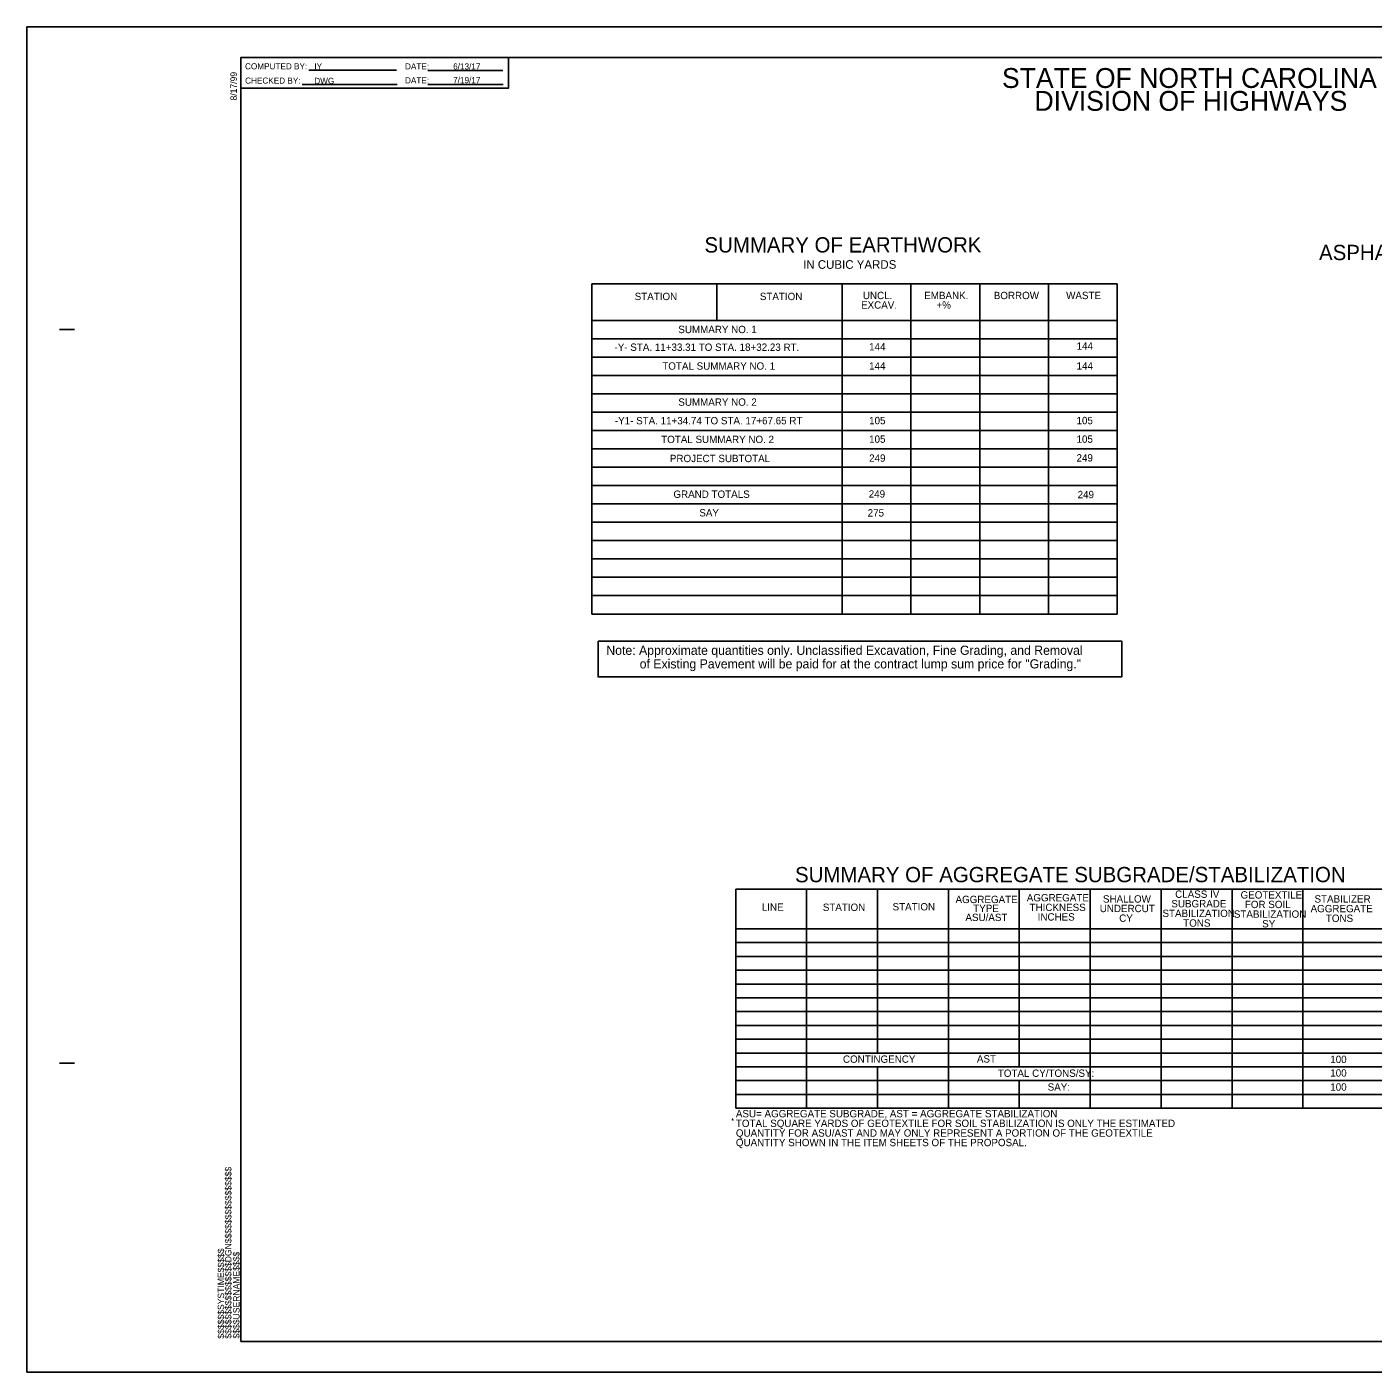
# Model space of a CAD drawing. Extents: x 573680 to 575380, y -53324 to -52224.
# Drawn here: x 573680 to 574781, y -53324 to -52224 of the extents above; entities that cross this region are included whole.
import ezdxf

# ---------------------------------------------------------------- set-up
doc = ezdxf.new("R2010")
doc.units = 0
for name, color, linetype in [('Prop Dimension Text', 7, 'Continuous'), ('Prop Grid Mask', 7, 'Continuous'), ('Prop XSC Text', 7, 'Continuous'), ('Sheet Block System Information CELL', 7, 'Continuous'), ('Sheet Data Field CELL', 7, 'Continuous'), ('Sheet Plan And Profile CELL', 7, 'Continuous'), ('Sheet Plot Border Outside CELL', 7, 'Continuous'), ('Sheet Summary Combination CELL', 7, 'Continuous'), ('Sheet Summary Combination Grid CELL', 7, 'Continuous')]:
    doc.layers.add(name, color=color, linetype=linetype)

msp = doc.modelspace()

# ---------------------------------------------------------------- linework, layer by layer
at = {"layer": 'Prop Grid Mask'}
msp.add_lwpolyline([(574147.2, -52726.6), (574575.6, -52726.6), (574575.6, -52755.8), (574147.2, -52755.8)], close=True, dxfattribs=at)
at = {"layer": 'Sheet Block System Information CELL'}
msp.add_line((573854.9, -53299.3), (573854.9, -53299.3), dxfattribs=at)
at = {"layer": 'Sheet Plan And Profile CELL'}
for p, q in [((573706.4, -52471.8), (573718.9, -52471.8)), ((573706.4, -53071.8), (573718.9, -53071.8)), ((573854.9, -53299.3), (573854.9, -53299.3)), ((573854.9, -53299.3), (573854.9, -53299.3)), ((573854.9, -53299.3), (573854.9, -53299.3)), ((573854.9, -53299.3), (573854.9, -53299.3)), ((573854.9, -53299.3), (573854.9, -53299.3))]:
    msp.add_line(p, q, dxfattribs=at)
msp.add_lwpolyline([(575354.9, -52249.3), (573854.9, -52249.3), (573854.9, -53299.3), (575354.9, -53299.3)], close=True, dxfattribs=at)
at = {"layer": 'Sheet Plot Border Outside CELL'}
msp.add_lwpolyline([(573679.9, -53324.3), (575379.9, -53324.3), (575379.9, -52224.3), (573679.9, -52224.3)], close=True, dxfattribs=at)
at = {"layer": 'Sheet Summary Combination CELL'}
for p, q in [((573910.5, -52259.7), (573982.1, -52259.7)), ((574007.9, -52259.9), (574069.3, -52259.9)), ((573905.1, -52271.4), (573982.8, -52271.4)), ((574008, -52271.4), (574069.4, -52271.4)), ((574273.2, -52434.4), (574273.2, -52434.4)), ((574280.7, -52434.6), (574280.7, -52434.6)), ((574291.6, -52434.3), (574291.6, -52434.3)), ((574298.3, -52434.4), (574298.3, -52434.4))]:
    msp.add_line(p, q, dxfattribs=at)
msp.add_lwpolyline([(573854.9, -52249.3), (574073.9, -52249.3), (574073.9, -52274.3), (573854.9, -52274.3)], close=True, dxfattribs=at)
at = {"layer": 'Sheet Summary Combination Grid CELL'}
for p, q in [((574142, -52434.4), (574571.9, -52434.4)), ((574142, -52434.4), (574142, -52599.4)), ((574244.4, -52434.4), (574244.4, -52464.4)), ((574346.8, -52434.4), (574346.8, -52599.4)), ((574403.1, -52434.4), (574403.1, -52599.4)), ((574459.4, -52434.4), (574459.4, -52599.2)), ((574515.6, -52434.4), (574515.6, -52600)), ((574571.9, -52434.4), (574571.9, -52599.4)), ((574142, -52464.4), (574571.9, -52464.4)), ((574142, -52479.4), (574571.9, -52479.4)), ((574142, -52494.4), (574571.9, -52494.4)), ((574142, -52509.4), (574571.9, -52509.4)), ((574142, -52524.4), (574571.9, -52524.4)), ((574142, -52539.4), (574571.9, -52539.4)), ((574142, -52554.4), (574571.9, -52554.4)), ((574142, -52569.4), (574571.9, -52569.4)), ((574142, -52584.4), (574571.9, -52584.4)), ((574142, -52599.4), (574571.9, -52599.4)), ((574142, -52599.4), (574571.9, -52599.4)), ((574142, -52599.4), (574142, -52614.4)), ((574346.8, -52597.4), (574346.8, -52704.4)), ((574403.1, -52599.3), (574403.1, -52704.4)), ((574459.4, -52599.4), (574459.4, -52704.4)), ((574515.6, -52598.9), (574515.6, -52704.4)), ((574571.9, -52599.4), (574571.9, -52614.4)), ((574142, -52614.4), (574571.9, -52614.4)), ((574142, -52614.4), (574142, -52629.4)), ((574571.9, -52614.4), (574571.9, -52629.4)), ((574142, -52629.4), (574571.9, -52629.4)), ((574142, -52629.4), (574142, -52644.4)), ((574571.9, -52629.4), (574571.9, -52644.4)), ((574142, -52644.4), (574571.9, -52644.4)), ((574142, -52644.4), (574142, -52659.4)), ((574571.9, -52644.4), (574571.9, -52659.4)), ((574142, -52659.4), (574571.9, -52659.4)), ((574142, -52659.4), (574142, -52674.4)), ((574571.9, -52659.4), (574571.9, -52674.4)), ((574142, -52674.4), (574571.9, -52674.4)), ((574142, -52674.4), (574142, -52689.4)), ((574571.9, -52674.4), (574571.9, -52689.4)), ((574142, -52689.4), (574571.9, -52689.4)), ((574142, -52689.4), (574142, -52704.4)), ((574571.9, -52689.4), (574571.9, -52704.4)), ((574142, -52704.4), (574571.9, -52704.4)), ((574259.8, -52929.5), (574839.8, -52929.5)), ((574259.8, -52929.5), (574259.8, -53108.5)), ((574317.8, -52929.5), (574317.8, -53108.5)), ((574375.8, -52929.5), (574375.8, -53063.4)), ((574433.8, -52929.5), (574433.8, -53108.5)), ((574491.8, -52929.5), (574491.8, -53074.7)), ((574549.8, -52929.5), (574549.8, -53108.5)), ((574607.8, -52929.5), (574607.8, -53108.5)), ((574665.8, -52929.5), (574665.8, -53108.5)), ((574723.8, -52929.5), (574723.8, -53108.5)), ((574259.8, -52961.8), (574839.8, -52961.8)), ((574259.8, -52973.1), (574839.8, -52973.1)), ((574259.8, -52984.4), (574839.8, -52984.4)), ((574259.8, -52995.7), (574839.8, -52995.7)), ((574259.8, -53007), (574513.7, -53007)), ((574259.8, -53007), (574839.8, -53007)), ((574259.8, -53018.2), (574839.8, -53018.2)), ((574259.8, -53029.5), (574839.8, -53029.5)), ((574259.8, -53040.8), (574839.8, -53040.8)), ((574259.8, -53052.1), (574839.8, -53052.1)), ((574259.8, -53063.4), (574839.8, -53063.4)), ((574259.8, -53074.7), (574839.8, -53074.7)), ((574375.8, -53074.7), (574375.8, -53108.5)), ((574259.8, -53085.9), (574839.8, -53085.9)), ((574491.8, -53085.9), (574491.8, -53108.5)), ((574259.8, -53097.2), (574839.8, -53097.2)), ((574259.8, -53108.5), (574839.8, -53108.5))]:
    msp.add_line(p, q, dxfattribs=at)

# ---------------------------------------------------------------- texts
at = {"layer": 'Prop Dimension Text'}
for s, p in [('AST', (574457.1, -53071.2)), ('100', (574746.2, -53071.6)), ('100', (574746.2, -53082.7)), ('100', (574746.2, -53094.2))]:
    msp.add_text(s, height=6, dxfattribs=at).set_placement(p)
at = {"layer": 'Prop XSC Text'}
for s, p in [('Note: Approximate quantities only. Unclassified Excavation, Fine Grading, and Removal', (574153.9, -52737.8)), ('of Existing Pavement will be paid for at the contract lump sum price for "Grading."', (574181.2, -52748.9))]:
    msp.add_text(s, height=7.5, dxfattribs=at).set_placement(p)
at = {"layer": 'Sheet Block System Information CELL'}
for s, p in [('$$$$$$$$$$$$$$$$DGN$$$$$$$$$$$$$$$$', (573847.2, -53297)), ('$$$$$$SYSTIME$$$$$', (573841.2, -53297)), ('$$$$USERNAME$$$$', (573853.8, -53296.9))]:
    msp.add_text(s, height=5.25, rotation=90, dxfattribs=at).set_placement(p)
at = {"layer": 'Sheet Data Field CELL'}
for s, p in [('IY', (573915, -52259)), ('6/13/17', (574028.6, -52259.1)), ('DWG', (573915, -52270.9)), ('7/19/17', (574028.6, -52270.3))]:
    msp.add_text(s, height=5, dxfattribs=at).set_placement(p)
at = {"layer": 'Sheet Plan And Profile CELL'}
msp.add_text('8/17/99', height=5.25, rotation=90, dxfattribs=at).set_placement((573851.6, -52284.5))
at = {"layer": 'Sheet Summary Combination CELL'}
for s, height, p in [('COMPUTED BY:', 5, (573858.3, -52259)), ('DATE:', 5, (573989.2, -52259.1)), ('STATE OF NORTH CAROLINA', 16.25, (574477.6, -52274.2)), ('CHECKED BY:', 5, (573858.4, -52270.7)), ('DATE:', 5, (573989.2, -52270.5)), ('DIVISION OF HIGHWAYS', 16.25, (574504.2, -52292.9)), ('STATION', 6, (574177.1, -52447.7)), ('STATION', 6, (574279.5, -52447.7)), ('UNCL.', 6, (574363.8, -52446.9)), ('EMBANK.', 6, (574414, -52446.9)), ('BORROW', 6, (574470.9, -52446.9)), ('WASTE', 6, (574530.1, -52446.9)), ('EXCAV.', 6, (574362.3, -52454.7)), ('+%', 6, (574424, -52454.7)), ('SUMMARY NO. 1 ', 6, (574212.8, -52474.7)), ('-Y- STA. 11+33.31 TO STA. 18+32.23 RT.', 6, (574160.6, -52489.2)), ('144', 6, (574368.9, -52488.9)), ('144', 6, (574538.6, -52488.3)), ('TOTAL SUMMARY NO. 1', 6, (574199.7, -52504.6)), ('144', 6, (574368.9, -52504.5)), ('144', 6, (574538.6, -52504.5)), ('SUMMARY NO. 2 ', 6, (574212.8, -52534.1)), ('-Y1- STA. 11+34.74 TO STA. 17+67.65 RT', 6, (574160.9, -52549.3)), ('105', 6, (574368.9, -52549.2)), ('105', 6, (574538.6, -52549.2)), ('TOTAL SUMMARY NO. 2', 6, (574198.8, -52564.6)), ('105', 6, (574368.9, -52564.4)), ('105', 6, (574538.6, -52564.4)), ('PROJECT SUBTOTAL', 6, (574205.9, -52580.2)), ('249', 6, (574368.9, -52579.9)), ('249', 6, (574538.6, -52579.7)), ('GRAND TOTALS', 6, (574208.8, -52609.4)), ('249', 6, (574368.6, -52609.2)), ('249', 6, (574539.5, -52609.7)), ('SAY', 6, (574230, -52624.6)), ('275', 6, (574367.7, -52624.7)), ('LINE', 6, (574281.1, -52947.1)), ('STATION', 6, (574331, -52947.2)), ('STATION', 6, (574388.1, -52946.8)), ('AGGREGATE', 6, (574439.6, -52940.8)), ('ASU/AST', 6, (574447.7, -52955.5)), ('TYPE', 6, (574454.1, -52948.1)), ('CONTINGENCY ', 6, (574347.5, -53071.4)), ('TOTAL CY/TONS/SY:', 6, (574474.2, -53082.9)), ('SAY:', 6, (574515, -53094.2)), ('*', 4.33, (574256.1, -53121)), ('ASU= AGGREGATE SUBGRADE, AST = AGGREGATE STABILIZATION', 6, (574259.9, -53116)), ('TOTAL SQUARE YARDS OF GEOTEXTILE FOR SOIL STABILIZATION IS ONLY THE ESTIMATED', 6, (574259.9, -53123.9)), ('QUANTITY FOR ASU/AST AND MAY ONLY REPRESENT A PORTION OF THE GEOTEXTILE', 6, (574259.9, -53131.8)), ('QUANTITY SHOWN IN THE ITEM SHEETS OF THE PROPOSAL.', 6, (574259.9, -53139.6))]:
    msp.add_text(s, height=height, dxfattribs=at).set_placement(p)
for s, height, p in [('SUMMARY OF EARTHWORK', 12.5, (574234.2, -52408.8)), ('ASPHALT PAVEMENT REMOVAL SUMMARY', 12.5, (574737, -52415)), ('IN CUBIC YARDS', 7.031, (574314.9, -52422.1)), ('SUMMARY OF AGGREGATE SUBGRADE/STABILIZATION', 12.5, (574308.3, -52923.8))]:
    msp.add_text(s, height=height, rotation=0.0119, dxfattribs=at).set_placement(p)
at = {"layer": 'Sheet Summary Combination Grid CELL'}
for s, p in [('CLASS IV', (574619.3, -52936.5)), ('GEOTEXTILE', (574672.8, -52937.1)), ('AGGREGATE', (574497.9, -52939.4)), ('THICKNESS', (574500.2, -52947.3)), ('SHALLOW', (574560.2, -52940.4)), ('SUBGRADE', (574616.2, -52944.3)), ('FOR SOIL', (574676.3, -52944.9)), ('STABILIZER', (574733.3, -52940.4)), ('INCHES', (574506.8, -52955.1)), ('UNDERCUT', (574557.6, -52948.2)), ('CY', (574573.5, -52956.1)), ('STABILIZATION', (574608.9, -52952.2)), ('STABILIZATION', (574667.3, -52952.8)), ('AGGREGATE', (574730.1, -52948.3)), ('TONS', (574742.6, -52956.2)), ('TONS', (574625.9, -52960.1)), ('SY', (574690.5, -52960.7))]:
    msp.add_text(s, height=6, dxfattribs=at).set_placement(p)

doc.saveas('drawing.dxf')
